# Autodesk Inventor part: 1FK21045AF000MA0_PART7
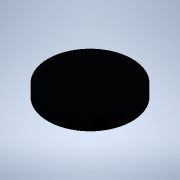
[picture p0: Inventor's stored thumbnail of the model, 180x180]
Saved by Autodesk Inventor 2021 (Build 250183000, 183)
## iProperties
Created: 2025-04
Part Number: 1FK21045AF000MA0_PART7
Material: Generic
Catalog Web Link: www.3dfindit.com
Description: -Servo synchronous motor
Document SubType Name: Modeling
Designer: psAdmin
Mass: 0.299142 g
Surface Area: 3.8585 cm^2
Volume: 0.299142 cm^3
Density: 1 g/cm^3
Appearance: PSOLRGB-38-46-56
Category: PARTsolutions
Title: 1FK21045AF000MA0_PART7
Author: Cadenas PARTsolutions
Comments: Servo synchronous motor
Sending System: PARTsolutions
Preprocessor: ST-DEVELOPER v19.3
PSOL_IDENT_0: {$CADENAS_DATA/23d-libs/siemens_ag/_cat_/8b/0a/1fk21045af000ma0.prj},213 {VTYP=3D},{NB=1FK21045AF000
PSOL_IDENT_1: MA0_PART7},{LINA=1FK21045AF000MA0_PART7},{NN=1FK21045AF000MA0_PART7},{NOPRJ=TRUE},{DATE=19.08.2025 1
PSOL_IDENT_2: 4:00:48},{GEOMDATE=30.07.2025 02:00:28},{VERSION=},{LINEID=10},{WBVAR=},{WBNUMERIC=}  {NB=1FK21045AF
PSOL_IDENT_3: 000MA0_PART7},{LINA=1FK21045AF000MA0_PART7},{KT=DUMMY},{PREVIEW=../../../_pool_/a9/69/p_d211_xx_0081
PSOL_IDENT_4: 8j.png},{DESCSHORT=SIMOTICS S-1FK2 HD, SINAMICS S210 3AC 400V-480V, 2.4 Nm, 3000 rpm},{DESCLONG=SIMO
PSOL_IDENT_5: TICS S-1FK2 HD servo motor M0=2.4 Nm; PN = 0.75 kW at nN=3000 rpm (380-480 V); PN = 0.375 kW at nN=1
PSOL_IDENT_6: 500 rpm (200-240 V); degree of protection IP64; cylindrical shaft D19x40mm; absolute encoder 22-bit
PSOL_IDENT_7: + 12-bit multiturn (encoder AM22DQC); with OCC interface; plug size M17, rotatable; SIMOTICS S-1FK2
PSOL_IDENT_8: servomotorfor a wide range of uses in industrial environments. SIMOTICS S‑1FK2 servomotors are compa
PSOL_IDENT_9: ct synchronous motors with a high dynamic performance that set themselves apart as a result of their
PSOL_IDENT_10: high power density, degree of protection and overload capability. The motors are available in two v
PSOL_IDENT_11: ariants: as High Dynamic variant (highest dynamic performance as a result of the low intrinsic momen
PSOL_IDENT_12: t of inertia for applications demanding a high dynamic performance with low moved masses) - and as C
PSOL_IDENT_13: ompact variant (precise and stable closed-loop control for medium up to large moved masses as a resu
PSOL_IDENT_14: lt of a medium intrinsic moment of inertia). SIMOTICSS‑1FK2 servomotors fully exploit their strength
PSOL_IDENT_15: s in a system with the SINAMICSS210 frequency converter and simple connection using the one cable co
PSOL_IDENT_16: nnection (OCC). Advantages include the short control and positioning times, fast and precise correct
PSOL_IDENT_17: ion of disturbing quantities as well as stable control with a high dynamic performance. The servo mo
PSOL_IDENT_18: tors can be configured to address a wide range of requirements. For example with and without holding
PSOL_IDENT_19: brake, IP64 or IP65 degree of protection, singleturn or multiturn absolute encoders - to name just
PSOL_IDENT_20: a few. Further, the servomotors are available in different shaft heights extending from 20 to 100. A
PSOL_IDENT_21: shaft sealing ring is available to achieve an IP65 degree of protection and for subsequent mounting
PSOL_IDENT_22: at the motor or as spare part. SIMOTICS - the optimum motor for each and every motion control appli
PSOL_IDENT_23: cation.},{INTNO=195125050112},{SUPPLIERALTNO=1FK2104-5AF00-0MA0},{MANUID=1FK21045AF000MA0},{MANUNAME=
PSOL_IDENT_24: Siemens},{MANUTYPEDESC=Synchronous motor 1FK2-HD 2.4 NM},{AAU732=SIMOTICS},{AAO057=S-1FK2},{AAU734=S
PSOL_IDENT_25: IMOTICS S-1FK2 HD servo motor M0=2.4 Nm; PN = 0.75 kW at nN=3000 rpm (380-480 V); PN = 0.375 kW at n
PSOL_IDENT_26: N=1500 rpm (200-240 V); degree of protection IP64; cylindrical shaft D19x40mm; absolute encoder 22-b
PSOL_IDENT_27: it + 12-bit multiturn (encoder AM22DQC); with OCC interface; plug size M17, rotatable;},{AAW338=Sync
PSOL_IDENT_28: hronous motor 1FK2-HD 2.4 NM},{AAO742=SIMOTICS},{AAO663=4042948692912},{NOCUPEROU=1},{PRICEQUANTITY=
PSOL_IDENT_29: 1},{QUANTITYMIN=1},{QUANTITYINT=1},{CTN=85015100},{COO=DE},{AAO676=1FK2104-5AF00-0MA0},{AAO677=Sieme
PSOL_IDENT_30: ns AG},{ORDERUNIT=C62},{CONTENTUNIT=C62}
NB: 1FK21045AF000MA0_PART7
NT: Servo synchronous motor
NBSYN: $MANUID._PART7
LINA: 1FK21045AF000MA0_PART7
CATALOG: SIEMENS
PREVIEW: ../../../_pool_/a9/69/p_d211_xx_00818j.png
DESCSHORT: SIMOTICS S-1FK2 HD, SINAMICS S210 3AC 400V-480V, 2.4 Nm, 3000 rpm
DESCLONG: SIMOTICS S-1FK2 HD servo motor M0=2.4 Nm; PN = 0.75 kW at nN=3000 rpm (380-480 V); PN = 0.375 kW at nN=1500 rpm (200-240 V); degree of protection IP64; cylindri
INTNO: 195125050112
SUPPLIERALTNO: 1FK2104-5AF00-0MA0
MANUID: 1FK21045AF000MA0
MANUNAME: Siemens
MANUTYPEDESC: Synchronous motor 1FK2-HD 2.4 NM
AAU732: SIMOTICS
AAO057: S-1FK2
AAU734: SIMOTICS S-1FK2 HD servo motor M0=2.4 Nm; PN = 0.75 kW at nN=3000 rpm (380-480 V); PN = 0.375 kW at nN=1500 rpm (200-240 V); degree of protection IP64; cylindri
AAW338: Synchronous motor 1FK2-HD 2.4 NM
AAO742: SIMOTICS
AAO663: 4042948692912.0
NOCUPEROU: 1
PRICEQUANTITY: 1
QUANTITYMIN: 1
QUANTITYINT: 1
CTN: 85015100
COO: DE
ARTICLENO: 1FK21045AF000MA0_PART7
BOMINFO: 1FK21045AF000MA0_PART7
CREATOR: CADENAS GmbH
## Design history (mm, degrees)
feature "2025_04_17_15_40_42_0734"
body "Solid1"
